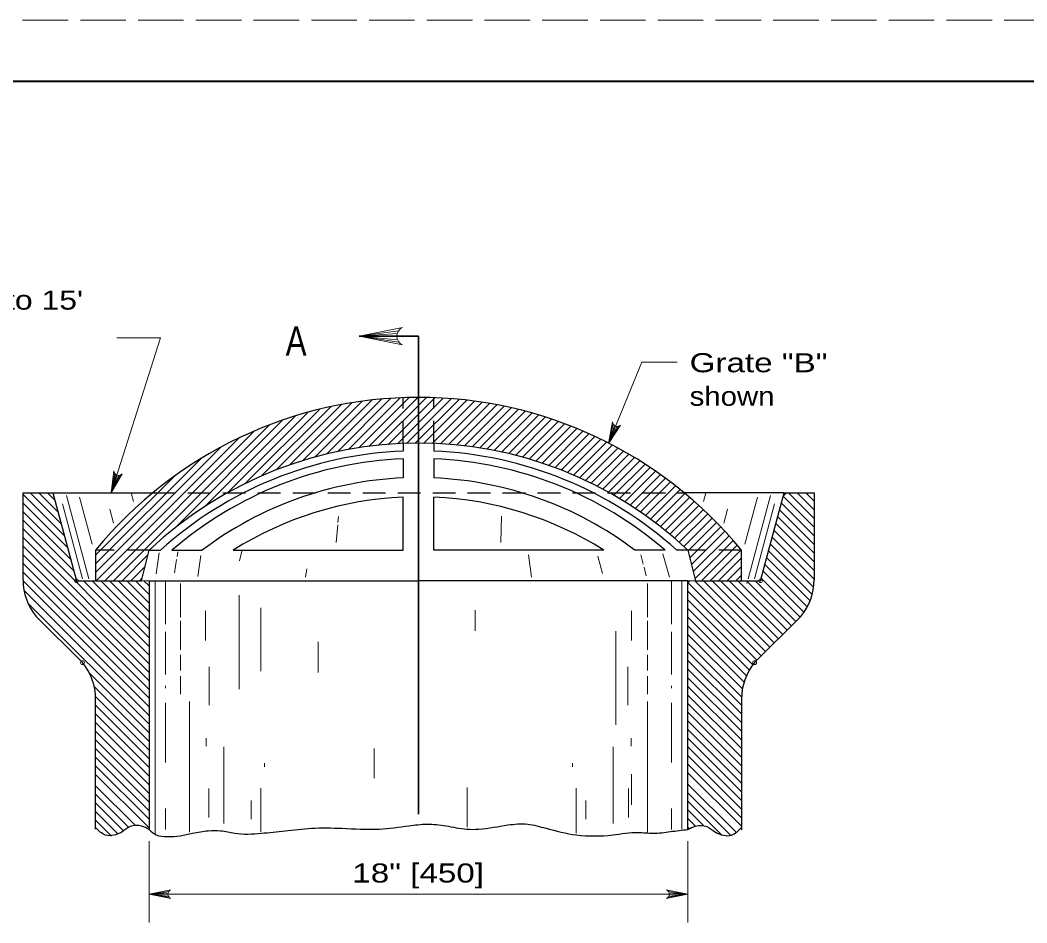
# Model space of a CAD drawing. Extents: x 1302.9 to 1336.9, y 688.5 to 710.5.
# Drawn here: x 1316.19 to 1324.42, y 703.12 to 710.5 of the extents above; entities that cross this region are included whole.
import ezdxf
from ezdxf.enums import TextEntityAlignment as Align

# ---------------------------------------------------------------- set-up
doc = ezdxf.new("R2010")
doc.units = 0
doc.header["$LTSCALE"] = 0.062
doc.header["$PDMODE"] = 32
doc.header["$PDSIZE"] = 0.031
doc.linetypes.add('LONG_DASHED', pattern=[7.5, 6, -1.5])
doc.linetypes.add('MEDIUM_DASHED', pattern=[4.5, 3, -1.5])
doc.layers.add('1', color=7, linetype='Continuous', lineweight=13)

msp = doc.modelspace()

# ---------------------------------------------------------------- linework, layer by layer
at = {"layer": '1', "lineweight": 25}
for p, q in [((1304.8765, 710.00158), (1336.3765, 710.00158)), ((1319.31983, 707.04075), (1319.31983, 706.97817)), ((1319.56975, 707.04075), (1319.56975, 706.97817)), ((1319.31983, 706.91575), (1319.31983, 706.75942)), ((1319.56975, 706.91575), (1319.56975, 706.75942)), ((1316.21192, 706.63708), (1316.45667, 706.63708)), ((1316.21192, 705.92617), (1316.21192, 706.63708)), ((1316.45667, 706.63708), (1317.27225, 706.63708)), ((1322.433, 706.63708), (1321.61742, 706.63708)), ((1322.24042, 705.91875), (1322.433, 706.63708)), ((1322.433, 706.63708), (1322.67775, 706.63708)), ((1322.67775, 706.63708), (1322.67775, 705.92617)), ((1319.31983, 706.16867), (1319.31983, 706.60317)), ((1319.56975, 706.16867), (1319.56975, 706.60317)), ((1316.80542, 706.16867), (1316.80542, 705.91875)), ((1317.24267, 706.16867), (1317.33483, 706.16867)), ((1317.42917, 706.16867), (1317.67742, 706.16867)), ((1317.92983, 706.16867), (1319.31983, 706.16867)), ((1320.95975, 706.16867), (1319.56975, 706.16867)), ((1321.46042, 706.16867), (1321.21225, 706.16867)), ((1321.64692, 706.16867), (1321.55483, 706.16867)), ((1322.08425, 705.91875), (1322.08425, 706.16867)), ((1317.24267, 705.91875), (1319.44483, 705.91875)), ((1317.24267, 705.91875), (1317.24267, 703.88133)), ((1321.64692, 705.91875), (1319.44483, 705.91875)), ((1321.64692, 703.8845), (1321.64692, 705.91875)), ((1322.08425, 705.91875), (1322.24042, 705.91875)), ((1316.69775, 705.24925), (1316.31933, 705.62758)), ((1322.57025, 705.62758), (1322.19183, 705.24925)), ((1316.80533, 703.88775), (1316.80525, 704.95067)), ((1322.08442, 704.95067), (1322.08425, 703.8835))]:
    msp.add_line(p, q, dxfattribs=at)
at = {"layer": '1'}
for p, q in [((1319.28117, 707.9625), (1318.96075, 707.91767)), ((1319.27033, 707.94025), (1318.96075, 707.91767)), ((1319.267, 707.91767), (1318.96075, 707.91767)), ((1319.27267, 707.88883), (1318.96075, 707.91767)), ((1319.285, 707.86808), (1318.96075, 707.91767)), ((1318.49708, 706.89992), (1318.9835, 707.38625)), ((1318.59675, 706.92875), (1319.06442, 707.3965)), ((1318.69167, 706.95308), (1319.14258, 707.404)), ((1318.78292, 706.97367), (1319.21942, 707.41008)), ((1318.87092, 706.991), (1319.29442, 707.41442)), ((1318.95617, 707.00558), (1319.36717, 707.4165)), ((1319.03825, 707.017), (1319.43908, 707.41767)), ((1319.11792, 707.026), (1319.50892, 707.41692)), ((1319.19575, 707.03317), (1319.57758, 707.41492)), ((1319.27158, 707.03833), (1319.64525, 707.41183)), ((1319.34508, 707.04108), (1319.711, 707.407)), ((1319.41742, 707.04275), (1319.7765, 707.40175)), ((1319.48792, 707.04258), (1319.83992, 707.3945)), ((1319.55675, 707.04075), (1319.90292, 707.38683)), ((1319.62475, 707.03808), (1319.96442, 707.37767)), ((1317.87925, 706.63533), (1318.53892, 707.29508)), ((1318.02692, 706.7125), (1318.63458, 707.32008)), ((1318.15917, 706.774), (1318.72667, 707.3415)), ((1318.27992, 706.82417), (1318.81475, 707.35883)), ((1318.392, 706.8655), (1318.90025, 707.37367)), ((1319.69058, 707.03325), (1320.02533, 707.36792)), ((1319.75583, 707.02775), (1320.085, 707.35683)), ((1319.81958, 707.02083), (1320.144, 707.34525)), ((1319.88217, 707.01283), (1320.20192, 707.3325)), ((1319.94392, 707.00383), (1320.25908, 707.319)), ((1320.00433, 706.9935), (1320.31542, 707.30458)), ((1317.44917, 706.34675), (1318.33408, 707.23158)), ((1317.70092, 706.52775), (1318.439, 707.26583)), ((1320.06408, 706.98267), (1320.371, 707.2895)), ((1320.12242, 706.97025), (1320.42558, 707.2735)), ((1320.1805, 706.95767), (1320.47975, 707.25692)), ((1320.23683, 706.94333), (1320.53292, 707.23933)), ((1320.29317, 706.929), (1320.58558, 707.22133)), ((1316.87975, 705.91875), (1318.10425, 707.14308)), ((1316.9505, 705.91875), (1318.223, 707.19125)), ((1320.34783, 706.913), (1320.63717, 707.20242)), ((1320.40242, 706.897), (1320.68867, 707.18308)), ((1320.4555, 706.87933), (1320.73875, 707.16258)), ((1320.50858, 706.86175), (1320.78892, 707.14208)), ((1321.03692, 707.1975), (1320.99808, 707.04042)), ((1321.04525, 707.18833), (1320.99808, 707.04042)), ((1321.05508, 707.18258), (1320.99808, 707.04042)), ((1321.08142, 707.18167), (1320.99808, 707.04042)), ((1321.0695, 707.17983), (1320.99808, 707.04042)), ((1316.80917, 705.91875), (1317.97567, 707.08517)), ((1320.56008, 706.84258), (1320.83775, 707.12017)), ((1320.61167, 706.8235), (1320.88658, 707.09825)), ((1320.66183, 706.80292), (1320.93417, 707.07525)), ((1320.71192, 706.78225), (1320.98158, 707.05208)), ((1316.80542, 705.98575), (1317.83242, 707.01267)), ((1320.76067, 706.7605), (1321.02825, 707.028)), ((1320.80933, 706.73842), (1321.07433, 707.00333)), ((1320.85692, 706.71533), (1321.11983, 706.97825)), ((1316.80542, 706.05633), (1317.66725, 706.91817)), ((1320.90417, 706.69183), (1321.16467, 706.95233)), ((1320.9505, 706.66758), (1321.20933, 706.92633)), ((1320.99642, 706.64275), (1321.25275, 706.89917)), ((1321.04167, 706.61742), (1321.29617, 706.87192)), ((1321.08617, 706.59125), (1321.33867, 706.84367)), ((1321.13033, 706.56475), (1321.38092, 706.81525)), ((1316.80542, 706.12708), (1317.45917, 706.78075)), ((1316.96133, 706.79625), (1316.93192, 706.63708)), ((1316.97017, 706.78758), (1316.93192, 706.63708)), ((1317.00667, 706.78308), (1316.93192, 706.63708)), ((1316.98033, 706.78242), (1316.93192, 706.63708)), ((1316.99492, 706.78058), (1316.93192, 706.63708)), ((1321.17358, 706.53725), (1321.4225, 706.78608)), ((1321.21675, 706.50975), (1321.46342, 706.75642)), ((1321.25867, 706.481), (1321.50408, 706.72642)), ((1316.21192, 706.63567), (1316.21333, 706.63708)), ((1316.45667, 706.63708), (1316.21192, 706.63708)), ((1316.52492, 706.38242), (1316.27025, 706.63708)), ((1316.499, 706.479), (1316.34083, 706.63708)), ((1316.47317, 706.57558), (1316.41158, 706.63708)), ((1317.11483, 706.56558), (1317.09567, 706.63708)), ((1321.30042, 706.45217), (1321.54383, 706.6955)), ((1321.34133, 706.42242), (1321.58358, 706.6645)), ((1321.77483, 706.56558), (1321.794, 706.63708)), ((1322.42608, 706.61133), (1322.45192, 706.63708)), ((1322.67775, 706.42758), (1322.46817, 706.63708)), ((1322.67775, 706.49817), (1322.53875, 706.63708)), ((1322.67775, 706.56892), (1322.6095, 706.63708)), ((1322.67775, 706.63567), (1322.67633, 706.63708)), ((1316.55075, 706.28592), (1316.21192, 706.62475)), ((1316.57667, 706.18942), (1316.21192, 706.55408)), ((1316.75092, 705.93433), (1316.56817, 706.616)), ((1316.77817, 706.21675), (1316.6745, 706.60325)), ((1321.382, 706.39225), (1321.62217, 706.6325)), ((1321.42192, 706.3615), (1321.66067, 706.60033)), ((1321.46117, 706.33025), (1321.6985, 706.5675)), ((1322.1115, 706.21675), (1322.21508, 706.60325)), ((1322.13875, 705.93433), (1322.3215, 706.616)), ((1322.67775, 706.28625), (1322.4105, 706.55333)), ((1322.67775, 706.35683), (1322.4255, 706.60917)), ((1316.60258, 706.09275), (1316.21192, 706.48342)), ((1316.69833, 705.93508), (1316.53408, 706.54783)), ((1316.95042, 706.39033), (1316.92008, 706.5035)), ((1321.50017, 706.2985), (1321.73583, 706.53408)), ((1321.53825, 706.26592), (1321.77283, 706.50042)), ((1321.93925, 706.39033), (1321.96958, 706.5035)), ((1322.19125, 705.93508), (1322.3555, 706.54783)), ((1322.67775, 706.2155), (1322.39558, 706.49758)), ((1316.6285, 705.99625), (1316.21192, 706.41275)), ((1318.7895, 706.44492), (1318.78525, 706.39383)), ((1320.122, 706.44558), (1320.11775, 706.2325)), ((1321.57633, 706.23325), (1321.80883, 706.46583)), ((1321.61325, 706.1995), (1321.84492, 706.43125)), ((1321.64817, 706.16383), (1321.88, 706.39558)), ((1322.67775, 706.14492), (1322.38067, 706.44192)), ((1317.24267, 705.31142), (1316.21192, 706.342)), ((1318.78375, 706.37617), (1318.77192, 706.2325)), ((1321.66225, 706.10725), (1321.91483, 706.35975)), ((1321.67642, 706.05075), (1321.94908, 706.32333)), ((1322.67775, 706.00358), (1322.35075, 706.3305)), ((1322.67775, 706.07417), (1322.36567, 706.38617)), ((1317.24267, 705.24075), (1316.21192, 706.27142)), ((1321.69058, 705.99417), (1321.98267, 706.28625)), ((1321.70467, 705.93758), (1322.01608, 706.24892)), ((1322.67775, 705.93283), (1322.33583, 706.27475)), ((1317.24267, 705.17008), (1316.21192, 706.20067)), ((1317.32558, 706.14608), (1317.30033, 705.97417)), ((1317.47617, 706.15608), (1317.47042, 706.11717)), ((1318.00158, 706.16108), (1317.9805, 706.08192)), ((1321.75658, 705.91875), (1322.0485, 706.21067)), ((1321.82717, 705.91875), (1322.081, 706.1725)), ((1322.08425, 706.16867), (1322.08425, 705.91875)), ((1322.662, 705.80725), (1322.306, 706.16325)), ((1322.67342, 705.8665), (1322.32092, 706.219)), ((1317.24267, 705.09942), (1316.21192, 706.13008)), ((1317.24267, 705.02875), (1316.21192, 706.05933)), ((1317.02108, 705.91875), (1317.23325, 706.13083)), ((1317.46683, 706.09242), (1317.45092, 705.98417)), ((1317.66608, 706.12433), (1317.64083, 705.95242)), ((1320.34325, 706.13033), (1320.36883, 705.94708)), ((1320.90917, 706.12058), (1320.94733, 705.97692)), ((1321.2615, 706.12967), (1321.28125, 706.05483)), ((1321.44092, 706.13883), (1321.49617, 705.94708)), ((1321.89792, 705.91875), (1322.08425, 706.10508)), ((1322.64475, 705.75392), (1322.291, 706.1075)), ((1317.24267, 704.95808), (1316.21192, 705.98875)), ((1317.09183, 705.91875), (1317.20967, 706.03667)), ((1318.53033, 706.01492), (1318.52083, 705.94708)), ((1321.28808, 706.02908), (1321.30642, 705.95983)), ((1321.96858, 705.91875), (1322.08425, 706.0345)), ((1322.59542, 705.66183), (1322.26117, 705.99608)), ((1322.62217, 705.70575), (1322.27608, 706.05175)), ((1317.24267, 704.88742), (1316.21208, 705.91783)), ((1317.24267, 705.38208), (1316.70592, 705.91875)), ((1317.24267, 705.45275), (1316.77658, 705.91875)), ((1317.24267, 705.52342), (1316.84725, 705.91875)), ((1317.24267, 705.59408), (1316.91792, 705.91875)), ((1317.24267, 705.66475), (1316.98867, 705.91875)), ((1317.24267, 705.73542), (1317.05925, 705.91875)), ((1317.24267, 705.80608), (1317.13, 705.91875)), ((1317.1625, 705.91875), (1317.18617, 705.94242)), ((1317.18025, 705.91875), (1317.24267, 705.91875)), ((1317.24267, 705.87675), (1317.20058, 705.91875)), ((1317.29217, 705.91875), (1317.29217, 703.84708)), ((1317.3765, 705.91875), (1317.3765, 705.56275)), ((1317.5, 705.89525), (1317.5, 705.62117)), ((1321.31675, 705.89525), (1321.31675, 705.62117)), ((1321.51308, 705.91875), (1321.51308, 705.56275)), ((1321.5975, 705.91875), (1321.5975, 703.88917)), ((1321.64692, 705.903), (1321.66275, 705.91875)), ((1321.64692, 705.91875), (1321.70942, 705.91875)), ((1322.24658, 705.304), (1321.64692, 705.9035)), ((1322.28192, 705.33925), (1321.70233, 705.91875)), ((1322.31725, 705.37458), (1321.773, 705.91875)), ((1322.3525, 705.41), (1321.84367, 705.91875)), ((1322.38792, 705.44533), (1321.91433, 705.91875)), ((1322.42325, 705.48058), (1321.985, 705.91875)), ((1322.03925, 705.91875), (1322.08425, 705.96375)), ((1322.45858, 705.51592), (1322.05575, 705.91875)), ((1322.49392, 705.55133), (1322.12642, 705.91875)), ((1322.12892, 705.89767), (1322.13458, 705.91875)), ((1322.52925, 705.58667), (1322.19708, 705.91875)), ((1322.56458, 705.62192), (1322.24617, 705.94033)), ((1317.24267, 704.81667), (1316.22067, 705.83858)), ((1322.21117, 705.26858), (1321.64692, 705.83283)), ((1317.24267, 704.746), (1316.25217, 705.7365)), ((1317.97783, 705.80017), (1317.97783, 705.03308)), ((1322.17808, 705.231), (1321.64692, 705.76208)), ((1317.70425, 705.43125), (1317.70425, 705.67233)), ((1318.1565, 705.17925), (1318.1565, 705.69792)), ((1319.90808, 705.67967), (1319.90808, 705.509)), ((1321.18542, 705.43125), (1321.18542, 705.67233)), ((1322.14992, 705.18858), (1321.64692, 705.6915)), ((1317.5, 705.592), (1317.5, 705.3545)), ((1321.31675, 705.592), (1321.31675, 705.3545)), ((1322.12558, 705.14225), (1321.64692, 705.62075)), ((1317.3765, 705.50067), (1317.3765, 705.15367)), ((1321.05775, 705.50792), (1321.05775, 704.74083)), ((1321.51308, 705.50067), (1321.51308, 705.15367)), ((1322.10625, 705.09092), (1321.64692, 705.55017)), ((1318.62342, 705.16825), (1318.62342, 705.42033)), ((1322.09242, 705.03408), (1321.64692, 705.47942)), ((1322.08483, 704.97092), (1321.64692, 705.40883)), ((1322.08442, 704.90067), (1321.64692, 705.33808)), ((1317.5, 705.31442), (1317.5, 705.1865)), ((1321.31675, 705.31442), (1321.31675, 705.1865)), ((1322.08442, 704.83008), (1321.64692, 705.2675)), ((1317.24267, 704.67533), (1316.75308, 705.16492)), ((1317.73333, 704.9015), (1317.73333, 705.21567)), ((1321.15625, 704.9015), (1321.15625, 705.21567)), ((1322.08442, 704.75933), (1321.64692, 705.19675)), ((1317.5, 705.139), (1317.5, 704.99292)), ((1321.31675, 705.139), (1321.31675, 704.99292)), ((1322.08442, 704.68875), (1321.64692, 705.12617)), ((1317.24267, 704.60475), (1316.79317, 705.05417)), ((1317.3765, 705.05858), (1317.3765, 705.04033)), ((1321.51308, 705.05858), (1321.51308, 705.04033)), ((1322.08442, 704.618), (1321.64692, 705.05542)), ((1317.24267, 704.534), (1316.80425, 704.97242)), ((1317.3765, 704.91983), (1317.3765, 704.434)), ((1317.57283, 704.93075), (1317.57283, 703.94083)), ((1321.31675, 704.93075), (1321.31675, 703.94083)), ((1321.51308, 704.91983), (1321.51308, 704.434)), ((1322.08442, 704.54742), (1321.64692, 704.98475)), ((1322.08433, 704.47667), (1321.64692, 704.91408)), ((1317.24267, 704.46333), (1316.80525, 704.90075)), ((1317.24267, 704.39267), (1316.80525, 704.83008)), ((1322.08433, 704.40608), (1321.64692, 704.84342)), ((1317.24267, 704.322), (1316.80525, 704.75942)), ((1322.08433, 704.33542), (1321.64692, 704.77275)), ((1317.24267, 704.25133), (1316.80525, 704.68875)), ((1322.08433, 704.26475), (1321.64692, 704.70208)), ((1317.24267, 704.18067), (1316.80525, 704.618)), ((1317.70792, 704.5655), (1317.70792, 704.63125)), ((1321.18175, 704.5655), (1321.18175, 704.63125)), ((1322.08433, 704.19408), (1321.64692, 704.63142)), ((1317.24267, 704.11), (1316.80525, 704.54742)), ((1317.85383, 704.56183), (1317.85383, 703.9335)), ((1319.08308, 704.30608), (1319.08308, 704.54717)), ((1321.03583, 704.56183), (1321.03583, 703.9335)), ((1322.08433, 704.12342), (1321.64692, 704.56075)), ((1317.24267, 704.03933), (1316.80533, 704.47667)), ((1318.18575, 704.42667), (1318.18575, 704.39742)), ((1320.70392, 704.42667), (1320.70392, 704.39742)), ((1322.08433, 704.05275), (1321.64692, 704.49008)), ((1322.08433, 703.98208), (1321.64692, 704.41942)), ((1317.24267, 703.96867), (1316.80533, 704.406)), ((1317.24267, 703.898), (1316.80533, 704.33533)), ((1321.18542, 704.08692), (1321.18542, 704.339)), ((1322.08433, 703.91142), (1321.64692, 704.34875)), ((1322.038, 703.86608), (1321.64692, 704.25708)), ((1317.13008, 703.91892), (1316.80533, 704.24367)), ((1317.07492, 703.90333), (1316.80533, 704.17292)), ((1318.1565, 704.22208), (1318.1565, 703.86583)), ((1319.84308, 704.22933), (1319.84308, 703.90317)), ((1320.73308, 704.22208), (1320.73308, 703.85642)), ((1321.99708, 703.83625), (1321.64692, 704.18642)), ((1317.034, 703.87358), (1316.80533, 704.10233)), ((1317.57283, 704.12217), (1317.57283, 703.86275)), ((1318.07625, 703.97008), (1318.07625, 704.1235)), ((1320.81333, 703.97008), (1320.81333, 704.1235)), ((1321.31675, 704.12217), (1321.31675, 703.86275)), ((1321.92025, 703.8425), (1321.64692, 704.11575)), ((1316.98683, 703.85017), (1316.80533, 704.03158)), ((1317.3765, 704.05633), (1317.3765, 703.88567)), ((1321.51308, 704.05633), (1321.51308, 703.88567)), ((1321.77558, 703.91642), (1321.64692, 704.045)), ((1316.9345, 703.83175), (1316.80533, 703.96092)), ((1321.70792, 703.91342), (1321.64692, 703.97442)), ((1321.65875, 703.89183), (1321.64692, 703.90367)), ((1317.24267, 703.791), (1317.24267, 703.12417)), ((1321.64692, 703.791), (1321.64692, 703.12417)), ((1317.40292, 703.37833), (1317.24267, 703.35592)), ((1317.3975, 703.36725), (1317.24267, 703.35592)), ((1317.39583, 703.35592), (1317.24267, 703.35592)), ((1317.39867, 703.34158), (1317.24267, 703.35592)), ((1317.40483, 703.33117), (1317.24267, 703.35592)), ((1321.48483, 703.33117), (1321.64692, 703.35592)), ((1321.48667, 703.37833), (1321.64692, 703.35592)), ((1321.49092, 703.34158), (1321.64692, 703.35592)), ((1321.49217, 703.36725), (1321.64692, 703.35592)), ((1321.49375, 703.35592), (1321.64692, 703.35592))]:
    msp.add_line(p, q, dxfattribs=at)
at = {"layer": '1', "lineweight": 35}
for p, q in [((1319.44483, 707.91767), (1318.96075, 707.91767)), ((1319.44483, 704.01067), (1319.44483, 707.91767))]:
    msp.add_line(p, q, dxfattribs=at)
at = {"layer": '1', "linetype": 'MEDIUM_DASHED', "lineweight": 25}
for p, q in [((1319.31983, 707.04075), (1319.31983, 707.41567)), ((1319.56975, 707.04075), (1319.56975, 707.41567)), ((1317.27225, 706.63708), (1321.61742, 706.63708)), ((1317.24267, 706.16867), (1316.80542, 706.16867)), ((1322.08425, 706.16867), (1321.64692, 706.16867))]:
    msp.add_line(p, q, dxfattribs=at)
at = {"layer": '1', "linetype": 'LONG_DASHED'}
msp.add_lwpolyline([(1302.8765, 688.50158), (1336.8765, 688.50158), (1336.8765, 710.50158), (1302.8765, 710.50158)], close=True, dxfattribs=at)
at = {"layer": '1', "lineweight": 40}
msp.add_lwpolyline([(1304.8765, 710.00158), (1336.3765, 710.00158), (1336.3765, 689.00158), (1304.8765, 689.00158)], close=True, dxfattribs=at)
msp.add_lwpolyline([(1304.8765, 710.00158), (1336.3765, 710.00158), (1336.3765, 689.00158), (1304.8765, 689.00158)], close=True, dxfattribs=at)
at = {"layer": '1'}
for points in [[(1319.31475, 707.84683), (1318.96075, 707.91767), (1319.31475, 707.98842)], [(1316.97808, 707.90483), (1317.33675, 707.90483), (1316.93192, 706.63708)], [(1320.99808, 707.04042), (1321.269, 707.70567), (1321.558, 707.70567)], [(1321.09683, 707.1915), (1320.99808, 707.04042), (1321.03117, 707.21783)], [(1317.0215, 706.79383), (1316.93192, 706.63708), (1316.95433, 706.81625)], [(1317.72975, 703.98333), (1317.72975, 704.06367), (1317.72975, 704.22075)], [(1321.15983, 703.98333), (1321.15983, 704.06367), (1321.15983, 704.22075)], [(1317.41967, 703.3205), (1317.24267, 703.35592), (1317.41967, 703.39133)], [(1317.24267, 703.35592), (1319.77767, 703.35592), (1321.64692, 703.35592)], [(1321.46992, 703.3205), (1321.64692, 703.35592), (1321.46992, 703.39133)]]:
    msp.add_lwpolyline(points, dxfattribs=at)
at = {"layer": '1', "lineweight": 25}
for points in [[(1316.45667, 706.63708), (1316.64925, 705.91875), (1316.80542, 705.91875)], [(1316.80542, 705.91875), (1317.18025, 705.91875), (1317.24267, 706.16867)], [(1321.64692, 706.16867), (1321.70942, 705.91875), (1322.08425, 705.91875)]]:
    msp.add_lwpolyline(points, dxfattribs=at)
at = {"layer": '1'}
for centre, radius, start, end in [((1319.3433, 707.91771), 0.0764, 112.08782, 247.91395), ((1321.06929, 707.21796), 0.0382, 180.20936, 316.03549), ((1316.99238, 706.81861), 0.0382, 183.64996, 319.47609), ((1317.43398, 703.35598), 0.0382, 112.08782, 247.91395), ((1321.45565, 703.35598), 0.0382, 292.08605, 67.91218)]:
    msp.add_arc(centre, radius, start, end, dxfattribs=at)
at = {"layer": '1', "lineweight": 25}
for centre, major_axis, start_param, end_param in [((1319.44482, 704.00564), (-3.41264, 0), 3.8281615, 5.5966165), ((1319.44482, 703.8338), (-3.20967, 0), 3.9562852, 5.4684928), ((1319.44482, 703.8338), (-3.1472, 0), 4.7520988, 5.4472029), ((1319.44482, 703.8338), (-3.1472, 0), 3.9775751, 4.6726792), ((1319.44482, 703.8338), (-3.08473, 0), 4.7529028, 5.4245044), ((1319.44482, 703.8338), (-3.08473, 0), 4.0002736, 4.6718752), ((1319.44482, 703.8338), (-2.92855, 0), 4.755065, 5.3602935), ((1319.44482, 703.8338), (-2.92855, 0), 4.0644845, 4.6697129), ((1319.44482, 703.76335), (2.84283, 0), 1.61476, 2.1328231), ((1319.44482, 703.76335), (2.84283, 0), 1.0087695, 1.5268326), ((1316.68045, 705.92619), (0.46853, 0), 3.1415927, 3.8325697), ((1322.20918, 705.92619), (-0.46853, 0), 2.4506156, 3.1415927), ((1316.3367, 704.95067), (-0.46853, 0), 3.1415927, 3.8325697), ((1322.55294, 704.95067), (0.46853, 0), 2.4506156, 3.1415927)]:
    msp.add_ellipse(centre, major_axis=major_axis, ratio=0.999895, start_param=start_param, end_param=end_param, dxfattribs=at)
for points in [[(1317.24267, 703.8855), (1317.1805, 703.91392), (1317.08725, 703.909), (1317.0185, 703.86483), (1316.88608, 703.84025), (1316.80542, 703.9005)], [(1317.24267, 703.8855), (1317.301, 703.84142), (1317.38867, 703.82792), (1317.49667, 703.83467), (1317.59783, 703.85492), (1317.726, 703.87508), (1317.82725, 703.87508), (1317.94192, 703.85492), (1318.15783, 703.85492), (1318.3535, 703.87508), (1318.56933, 703.89542), (1318.81892, 703.89542), (1319.12258, 703.88867), (1319.36542, 703.91567), (1319.51383, 703.92917), (1319.66908, 703.91567), (1319.83767, 703.88867), (1319.93883, 703.88867), (1320.175, 703.92242), (1320.33692, 703.92917), (1320.48533, 703.89542), (1320.73492, 703.84142), (1321.03183, 703.84142), (1321.24092, 703.86167), (1321.36233, 703.85492), (1321.504, 703.86842), (1321.64692, 703.8855)], [(1321.64692, 703.8855), (1321.70917, 703.91392), (1321.80233, 703.909), (1321.87108, 703.86483), (1322.0035, 703.84025), (1322.08425, 703.9005)]]:
    msp.add_spline(points, degree=3, dxfattribs=at)
at = {"layer": '1'}
for p in [(1316.64925, 705.91875), (1322.24042, 705.91875), (1316.69775, 705.24925), (1322.19183, 705.24925)]:
    msp.add_point(p, dxfattribs=at)

# ---------------------------------------------------------------- texts
for s, height, width, p in [("returning to normal within 10' to 15'", 0.156, 1.25, (1312.66033, 708.13517)), ('A', 0.24, 0.8, (1318.35842, 707.75825)), ('Grate "B"', 0.156, 1.3, (1321.66075, 707.62308)), ('shown', 0.156, 1.15, (1321.66075, 707.34908))]:
    msp.add_text(s, height=height, dxfattribs=dict(at, width=width)).set_placement(p)
at = {"layer": '1', "width": 1.3}
msp.add_text('18" [450]', height=0.156, dxfattribs=at).set_placement((1319.44154, 703.45167), align=Align.CENTER)

doc.saveas('drawing.dxf')
